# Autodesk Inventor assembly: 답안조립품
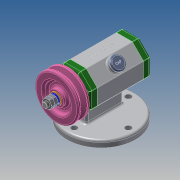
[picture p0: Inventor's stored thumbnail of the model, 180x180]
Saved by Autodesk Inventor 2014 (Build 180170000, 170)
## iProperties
Created: 2021-02
Part Number: 답안조립품
Document SubType Name: Assembly
Designer: kb542-18
Author: kb542-18
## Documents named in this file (14)
- C:\Users\kb542-18\Desktop\710204V1015\답안조립품.iam
- C:\Users\kb542-18\Desktop\710204V1015\본체.ipt
- C:\Users\kb542-18\Desktop\710204V1015\V벨트풀리.ipt
- C:\Users\kb542-18\Desktop\710204V1015\고무캡.ipt
- C:\Users\kb542-18\Desktop\710204V1015\너트 M8.ipt
- C:\Users\kb542-18\Desktop\710204V1015\뒤커버.ipt
- C:\Users\kb542-18\Desktop\710204V1015\베어링 15 x 32 x 9.ipt
- C:\Users\kb542-18\Desktop\710204V1015\볼트 M4 x 12.ipt
- C:\Users\kb542-18\Desktop\710204V1015\스프링와셔 8.ipt
- C:\Users\kb542-18\Desktop\710204V1015\앞커버.ipt
- C:\Users\kb542-18\Desktop\710204V1015\오일 실 15 25 7.ipt
- C:\Users\kb542-18\Desktop\710204V1015\와셔 8x17.ipt
- C:\Users\kb542-18\Desktop\710204V1015\축.ipt
- C:\Users\kb542-18\Desktop\710204V1015\키 3 x 3 x 12.ipt
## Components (2 placed, 2 different names)
1. V벨트풀리:1 — 각도:3
2. 고무캡:1
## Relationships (1: Angle 1)
- 각도:3 [Angle]: V벨트풀리:1
